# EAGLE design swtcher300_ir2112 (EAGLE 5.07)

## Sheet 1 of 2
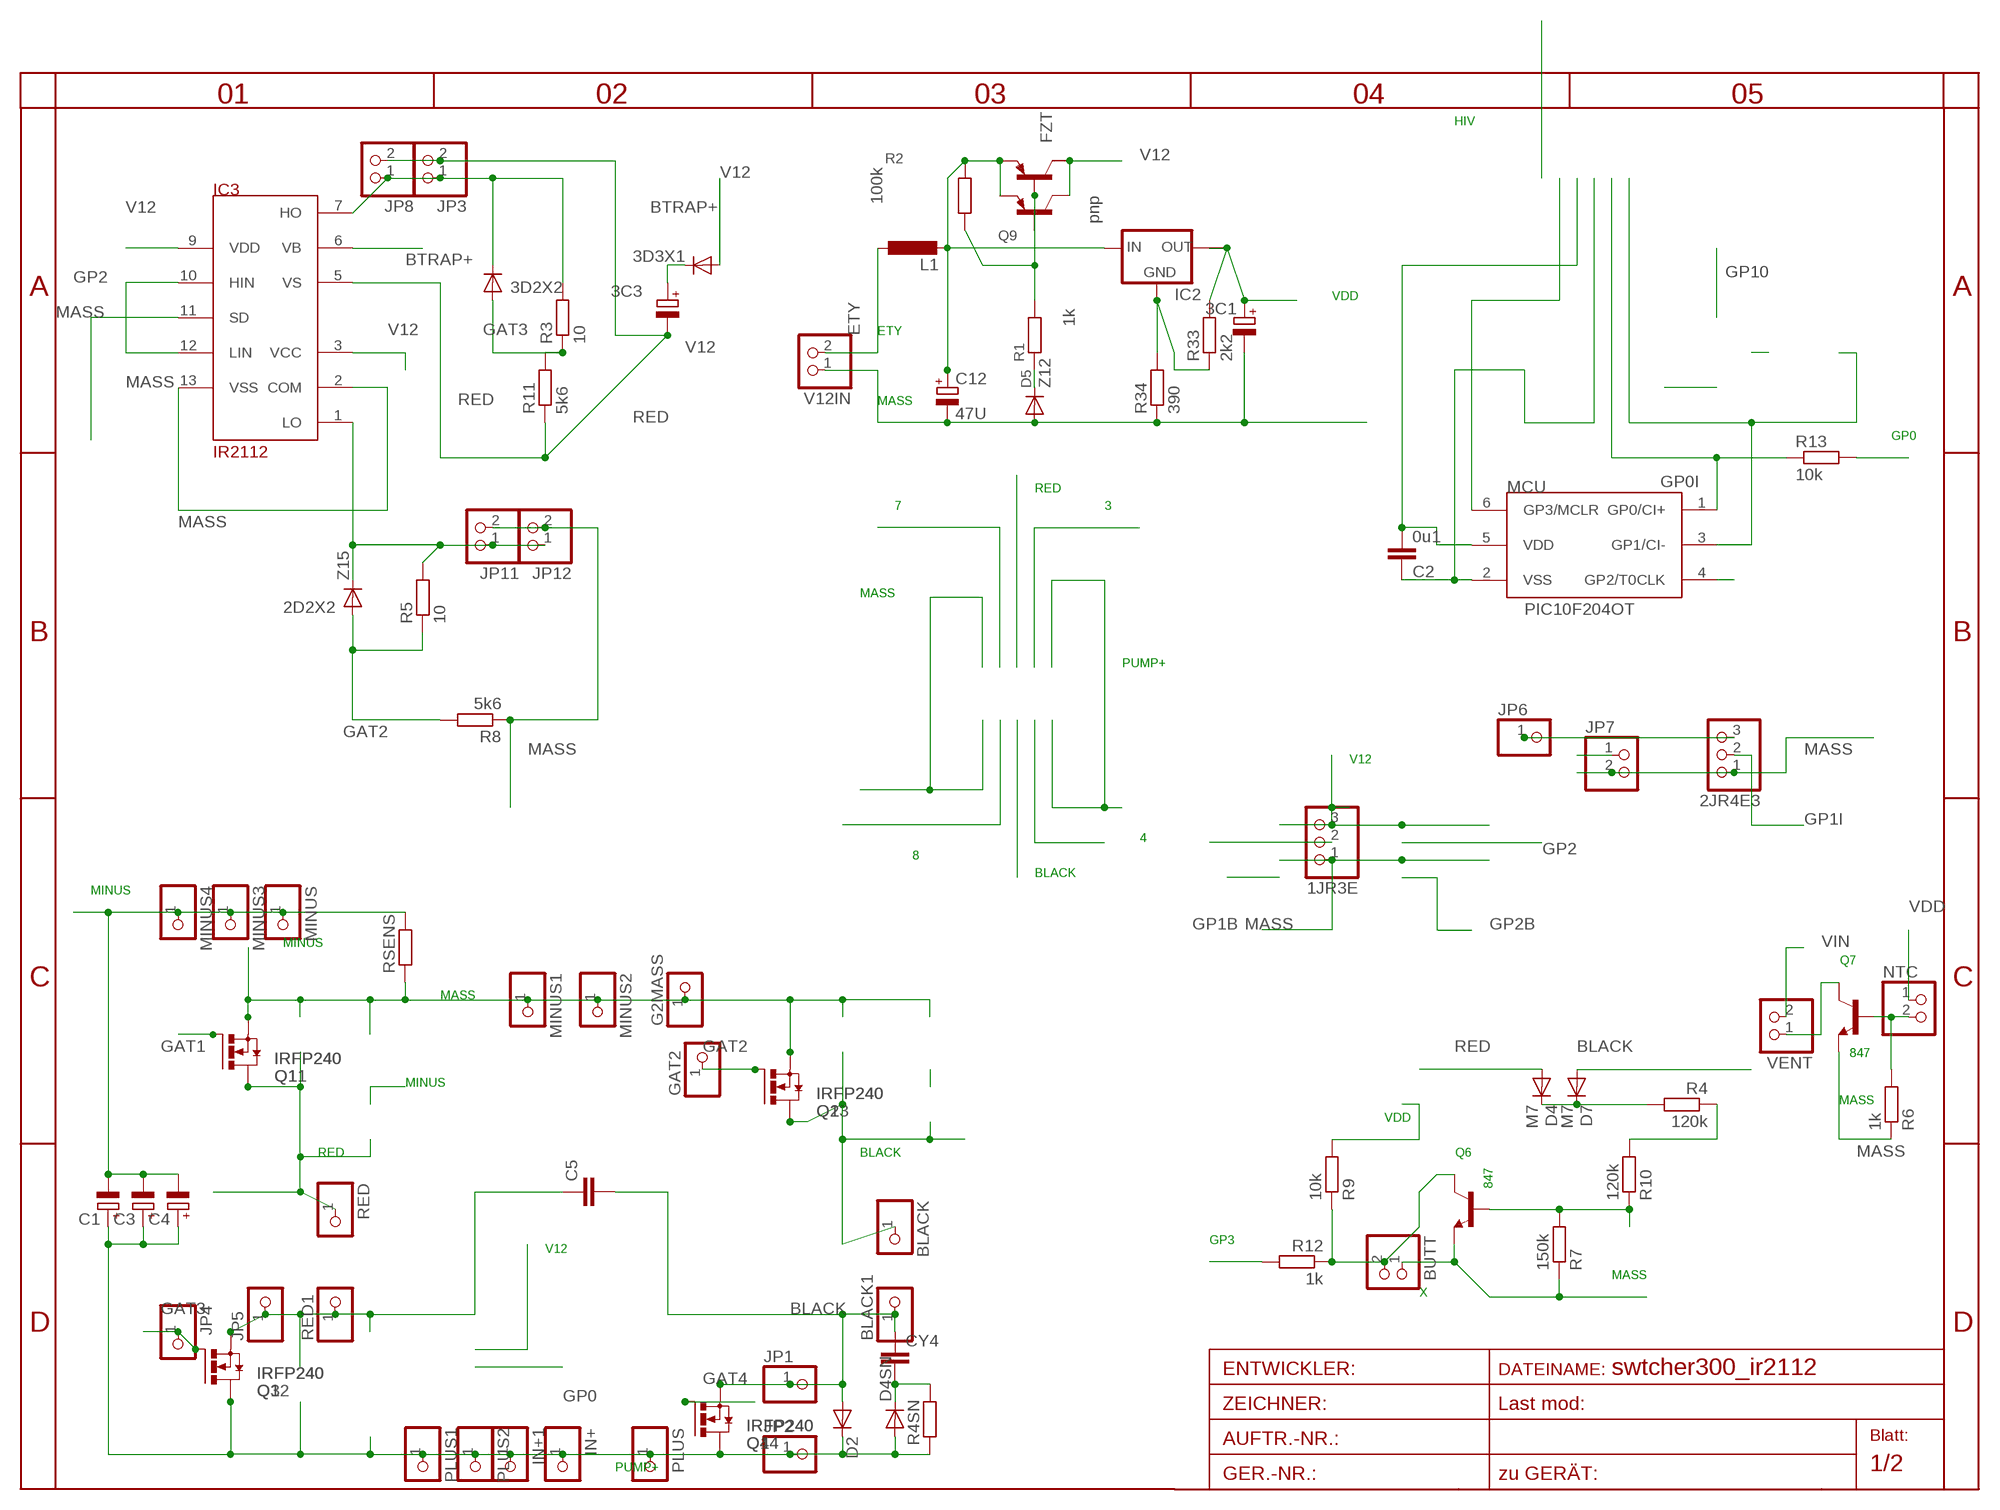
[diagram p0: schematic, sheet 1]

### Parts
1JR3E  PINHD-1X3  [1X03]
2D2X2  Z15  DIODE-D-7.5  [D-7.5]
2JR4E3  PINHD-1X3  [1X03]
3C1  CPOL-EUD  [PANASONIC_D]
3C3  CPOL-EUE2.5-5  [E2,5-5]
3D2X2  DIODE-D-7.5  [D-7.5]
3D3X1  DIODE-D-7.5  [D-7.5]
BLACK  PINHD-1X12MM3  [1X2MM3]
BLACK1  PINHD-1X12MM3  [1X2MM3]
BUTT  PINHD-1X2STR  [1X02]
C1  CPOL-EUE5-13  [E5-13]
C2  0u1  C-EUC0805  [C0805]
C3  CPOL-EUE5-13  [E5-13]
C4  CPOL-EUE5-13  [E5-13]
C5  C-EU075-032X103  [C075-032X103]
C12  47U  CPOL-EUSMCA  [SMC_A]
CY4  CXXC10B5  [XC10B5]
D2  DIODE-SMC  [SMC]
D4  M7  1N4004DO41-10  [DO41-10]
D4SN  DIODE-P1-10  [P1-10]
D5  Z12  DIODE-MINIMELF  [MINIMELF]
D7  M7  1N4004DO41-10  [DO41-10]
FZT  FZT  FZT753SMD  [SOT223]
G2MASS  PINHD-1X11MM0  [1X1MM0]
GAT2  PINHD-1X11MM0  [1X1MM0]
IC2  AP1117  [SOT223]
IC3  IR2112  [DIL14]
IN+  PINHD-1X12MM3  [1X2MM3]
IN+1  PINHD-1X12MM3  [1X2MM3]
JP1  PINHD-1X11MM0  [1X1MM0]
JP2  PINHD-1X11MM0  [1X1MM0]
JP3  PINHD-1X2STR  [1X02]
JP4  PINHD-1X11MM0  [1X1MM0]
JP5  PINHD-1X11MM0  [1X1MM0]
JP6  PINHD-1X11X0.4  [1X01]
JP7  PINHD-1X2STR  [1X02]
JP8  PINHD-1X2STR  [1X02]
JP11  PINHD-1X2STR  [1X02]
JP12  PINHD-1X2STR  [1X02]
L1  L-EU0204/5  [0204/5]
MCU  PIC10F204OT  [SOT23-6]
MINUS  PINHD-1X12MM3  [1X2MM3]
MINUS1  PINHD-1X12MM3  [1X2MM3]
MINUS2  PINHD-1X12MM3  [1X2MM3]
MINUS3  PINHD-1X12MM3  [1X2MM3]
MINUS4  PINHD-1X12MM3  [1X2MM3]
NTC  PINHD-1X2STR  [1X02]
PLUS  PINHD-1X12MM3  [1X2MM3]
PLUS1  PINHD-1X12MM3  [1X2MM3]
PLUS2  PINHD-1X12MM3  [1X2MM3]
Q1  IRFP240  [TO247BV]
Q2  IRFP240  [TO247BV]
Q3  IRFP240  [TO247BV]
Q4  IRFP240  [TO247BV]
Q6  847  BC847ALT1SMD  [SOT23]
Q7  847  BC847ALT1SMD  [SOT23]
Q9  pnp  BC857ALT1SMD  [SOT23-BEC]
Q11  IRFP240  [TO247BV]
Q12  IRFP240  [TO247BV]
Q13  IRFP240  [TO247BV]
Q14  IRFP240  [TO247BV]
R1  1k  R-EU_R0805  [R0805]
R2  100k  R-EU_R0805  [R0805]
R3  10  R-EU_0204/7  [0204/7]
R4  120k  R-EU_R1210  [R1210]
R4SN  R-EU_0207/10  [0207/10]
R5  10  R-EU_0204/7  [0204/7]
R6  1k  R-EU_R0805  [R0805]
R7  150k  R-EU_R0805  [R0805]
R8  5k6  R-EU_0207/10  [0207/10]
R9  10k  R-EU_R0805  [R0805]
R10  120k  R-EU_R1210  [R1210]
R11  5k6  R-EU_0207/10  [0207/10]
R12  1k  R-EU_R0805  [R0805]
R13  10k  R-EU_R0805  [R0805]
R33  2k2  R-EU_R0805  [R0805]
R34  390  R-EU_R0805  [R0805]
RED  PINHD-1X12MM3  [1X2MM3]
RED1  PINHD-1X12MM3  [1X2MM3]
RSENS  R-EU_0204/7  [0204/7]
V12IN  PINHD-1X2STR  [1X02]
VENT  PINHD-1X2STR  [1X02]

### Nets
BLACK: BLACK1.1 BLACK.1 C5.2 CY4.1 D2.A D7.A JP1.1 Q2.D Q4.S Q13.D Q14.S
BTRAP+: 3C3.+ 3D3X1.C IC3.6(VB)
ETY: L1.1 V12IN.2
GAT1: Q1.G Q11.G
GAT2: 2D2X2.A GAT2.1 Q2.G Q13.G R5.1 R8.2
GAT3: 3D2X2.A JP4.1 Q3.G Q12.G R3.1 R11.2
GAT4: Q4.G Q14.G
GGG: 3D2X2.C IC3.7(HO) JP3.1 JP8.1 R3.2
GP0: R13.2
GP0I: MCU.1(GP0/CI+) R13.1 ; also sheet 2
GP1I: 2JR4E3.2 MCU.3(GP1/CI-) ; also sheet 2
GP2: IC3.10(HIN) IC3.12(LIN) JP7.1 MCU.4(GP2/T0CLK)
GP2I: 1JR3E.2 ; also sheet 2
GP3: MCU.6(GP3/MCLR) R12.2 ; also sheet 2
LOGAT: 2D2X2.C IC3.1(LO) JP11.1 JP12.1 R5.2
MASS: 1JR3E.1 2JR4E3.1 3C1.- BUTT.1 C2.1 C12.- D5.A G2MASS.1 IC3.2(COM) IC3.11(SD) IC3.13(VSS) JP7.2 JP11.2 JP12.2 MCU.2(VSS) MINUS1.1 MINUS2.1 Q1.S Q2.S Q6.2(E) Q7.2(E) Q11.S Q13.S R6.1 R7.1 R8.1 R34.1 RSENS.1 V12IN.1 ; also sheet 2
MINUS: C1.- C3.- C4.- MINUS3.1 MINUS4.1 MINUS.1 RSENS.2
N$1: D4.C D7.C R4.2
N$2: FZT.1(B) Q9.B R1.2 R2.1
N$3: D5.C R1.1
N$5: Q6.1(B) R7.2 R10.1
N$7: R4.1 R10.2
N$9: NTC.2 Q7.1(B) R6.2
N$10: Q7.3(C) VENT.1
N$30: IC2.1(GND) R33.1 R34.2
PUMP+: C1.+ C3.+ C4.+ D2.C D4SN.A IN+1.1 IN+.1 JP2.1 PLUS1.1 PLUS2.1 PLUS.1 Q3.D Q4.D Q12.D Q14.D R4SN.1 ; also sheet 2
RED: 3C3.- C5.1 D4.A IC3.5(VS) JP3.2 JP5.1 JP8.2 Q1.D Q3.S Q11.D Q12.S R11.1 RED1.1 RED.1
SNUB2: CY4.2 D4SN.C R4SN.2
V12: 1JR3E.3 2JR4E3.3 3D3X1.A FZT.2(C) IC3.3(VCC) IC3.9(VDD) JP6.1 Q9.C
VDD: 3C1.+ C2.2 IC2.2(OUT) IC2.4(TAB) MCU.5(VDD) NTC.1 R9.2 R33.2 ; also sheet 2
VIN: C12.+ FZT.3(E) IC2.3(IN) L1.2 Q9.E R2.2 VENT.2
X: BUTT.2 Q6.3(C) R9.1 R12.1
Unconnected: FZT.4(C/)

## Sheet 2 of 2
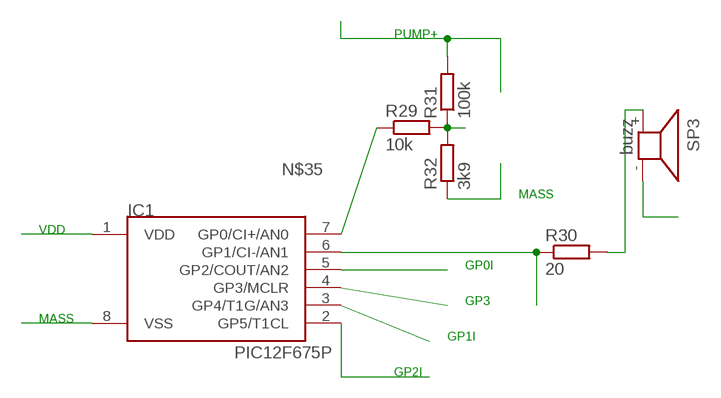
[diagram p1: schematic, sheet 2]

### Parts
IC1  PIC12F675P  [DIL8]
R29  10k  R-EU_R0805  [R0805]
R30  20  R-EU_R0805  [R0805]
R31  100k  R-EU_0207/25  [0207/25]
R32  3k9  R-EU_R0805  [R0805]
SP3  buzz  KSS12017MM  [KSS1202]

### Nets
GP0I: IC1.5(GP2/COUT/AN2) ; also sheet 1
GP1I: IC1.3(GP4/T1G/AN3) ; also sheet 1
GP2I: IC1.2(GP5/T1CL) ; also sheet 1
GP3: IC1.4(GP3/MCLR) ; also sheet 1
MASS: IC1.8(VSS) R32.1 SP3.- ; also sheet 1
N$24: R30.2 SP3.+
N$31: IC1.6(GP1/CI-/AN1) R30.1
N$34: R29.2 R31.1 R32.2
N$35: IC1.7(GP0/CI+/AN0) R29.1
PUMP+: R31.2 ; also sheet 1
VDD: IC1.1(VDD) ; also sheet 1

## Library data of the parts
1JR3E 2JR4E3 = pinhead:PINHD-1X3: PIN HEADER
2D2X2 3D2X2 3D3X1 D2 D4SN D5 = diode:DIODE-: DIODE
3C1 3C3 C1 C3 C4 = rcl:CPOL-EU: POLARIZED CAPACITOR, European symbol
BLACK BLACK1 G2MASS GAT2 IN+ IN+1 JP1 JP2 JP4-JP6 MINUS MINUS1-MINUS4 PLUS PLUS1 PLUS2 RED RED1 = pinhead:PINHD-1X1: PIN HEADER
BUTT JP3 JP7 JP8 JP11 JP12 NTC V12IN VENT = pinhead:PINHD-1X2: PIN HEADER
C2 C5 = rcl:C-EU: CAPACITOR, European symbol
C12 = rcl-2:CPOL-EU: POLARIZED CAPACITOR, European symbol
CY4 = rcl:CX: X CAPACITOR
D4 D7 = diode:1N4004: DIODE
FZT = transistor-pnp:FZT753SMD: PNP Transistor
IC1 = microchip-5:PIC12F6*: uPC nW 1k Program Flash memory 2x Timer Comparator 10b A/D converter/ 4xIN
IC2 = v-reg:AP1117
IC3 = ir2112:IR2112
L1 = rcl:L-EU: INDUCTOR, European symbol
MCU = microchip-3:PIC10F2*: uPC nW 0,25/0,5k Program Flash memory Comparator
Q1-Q4 Q11-Q14 = transistor-power:IRFP240: HEXFET Power MosFet Source: http://www.irf.com/
Q6 Q7 = transistor-npn:BC847*: NPN Transistor
Q9 = transistor-pnp:BC857*: PNP Transistror
R1-R3 R5 R8 R11 R13 R29-R34 = rcl-2:R-EU_: RESISTOR, European symbol
R4 R4SN R6 R7 R9 R10 R12 RSENS = rcl:R-EU_: RESISTOR, European symbol
SP3 = buzzer:KSS1201: SPEAKER

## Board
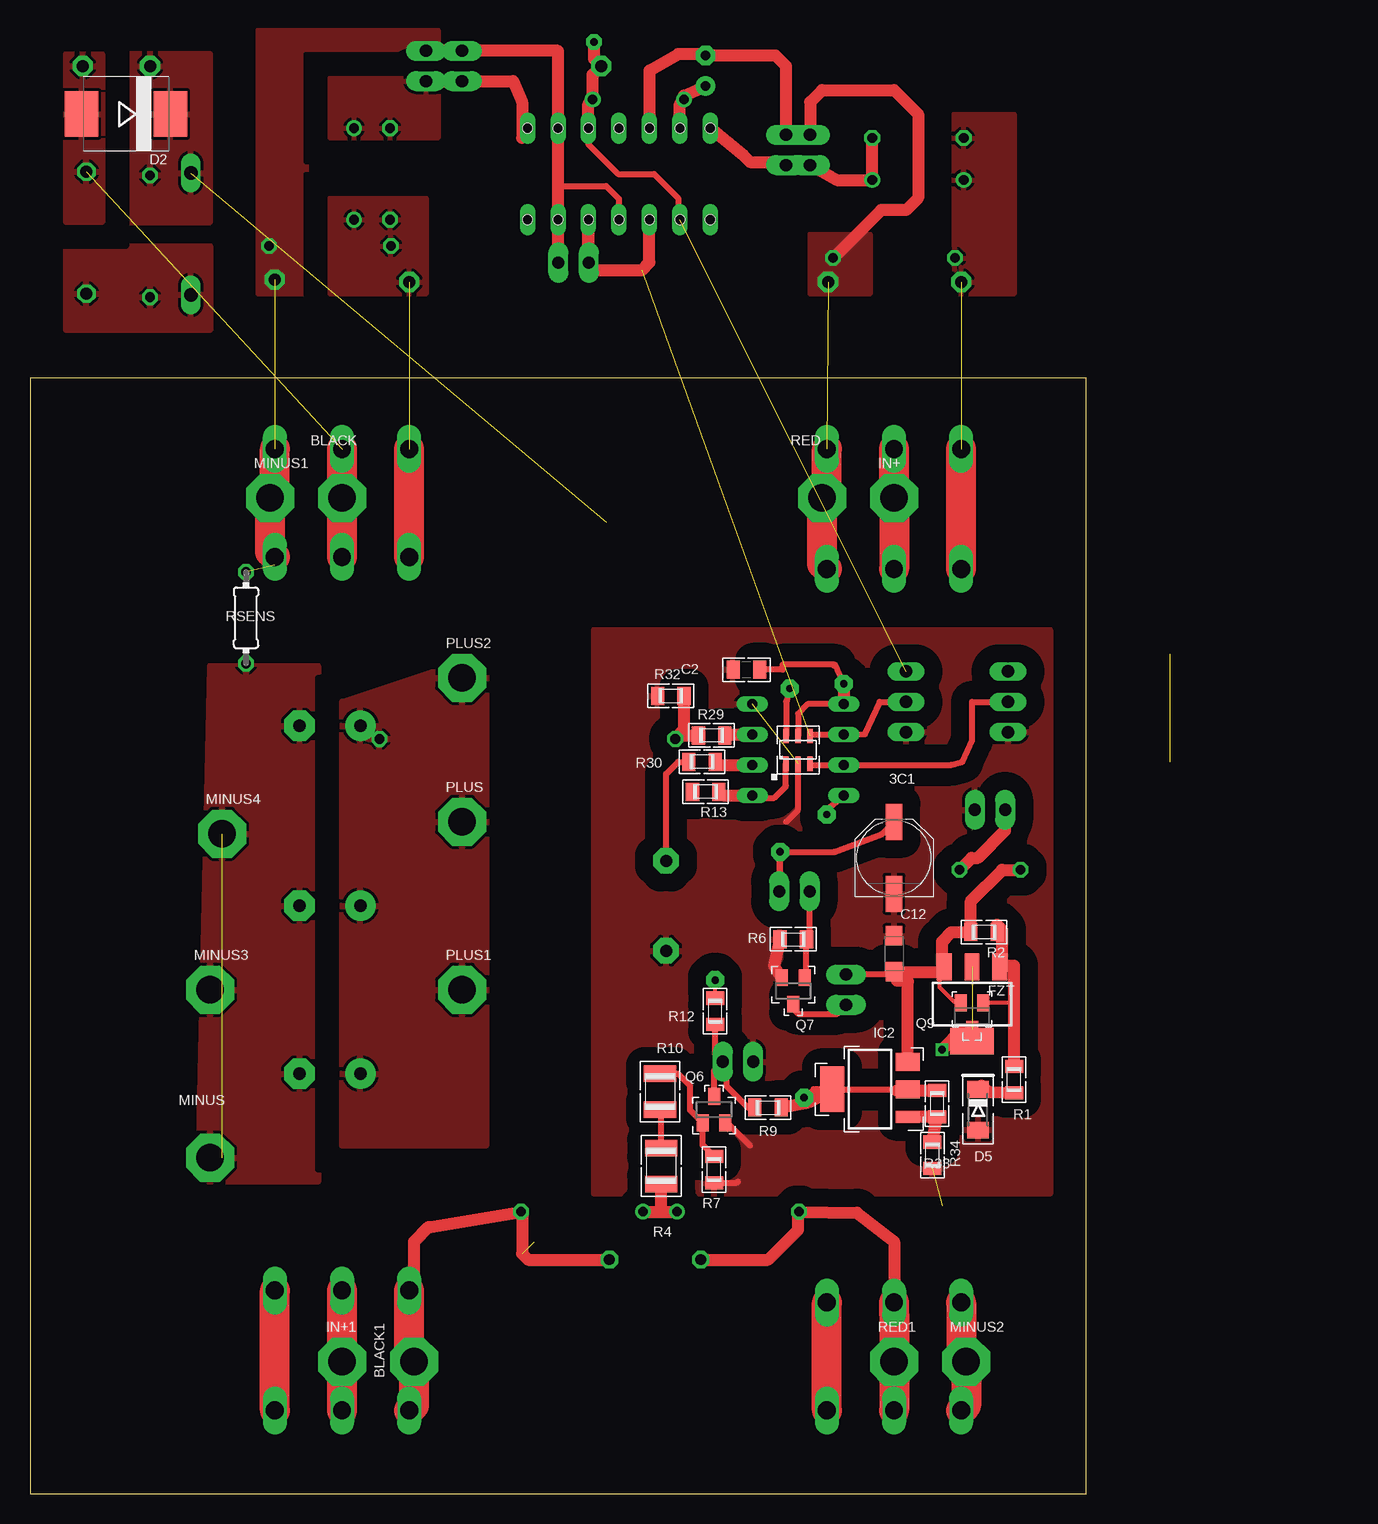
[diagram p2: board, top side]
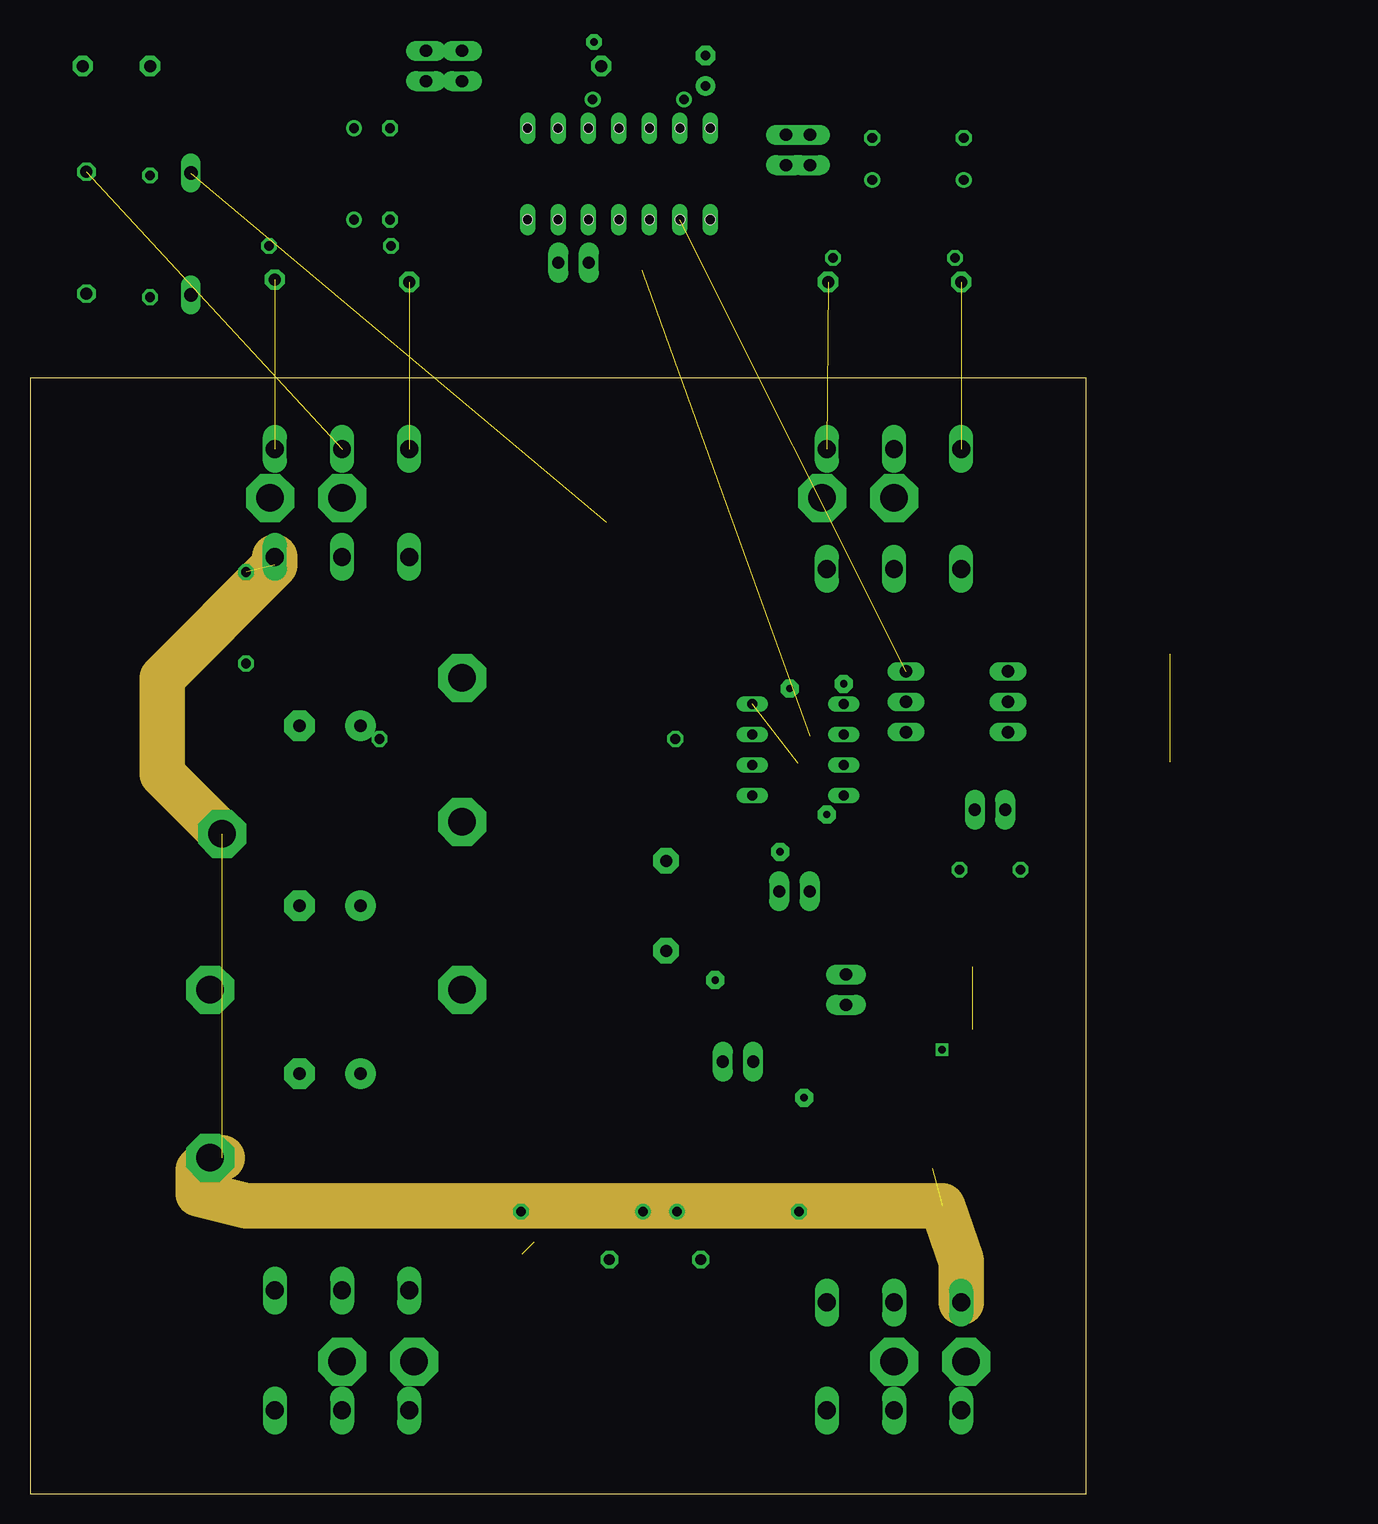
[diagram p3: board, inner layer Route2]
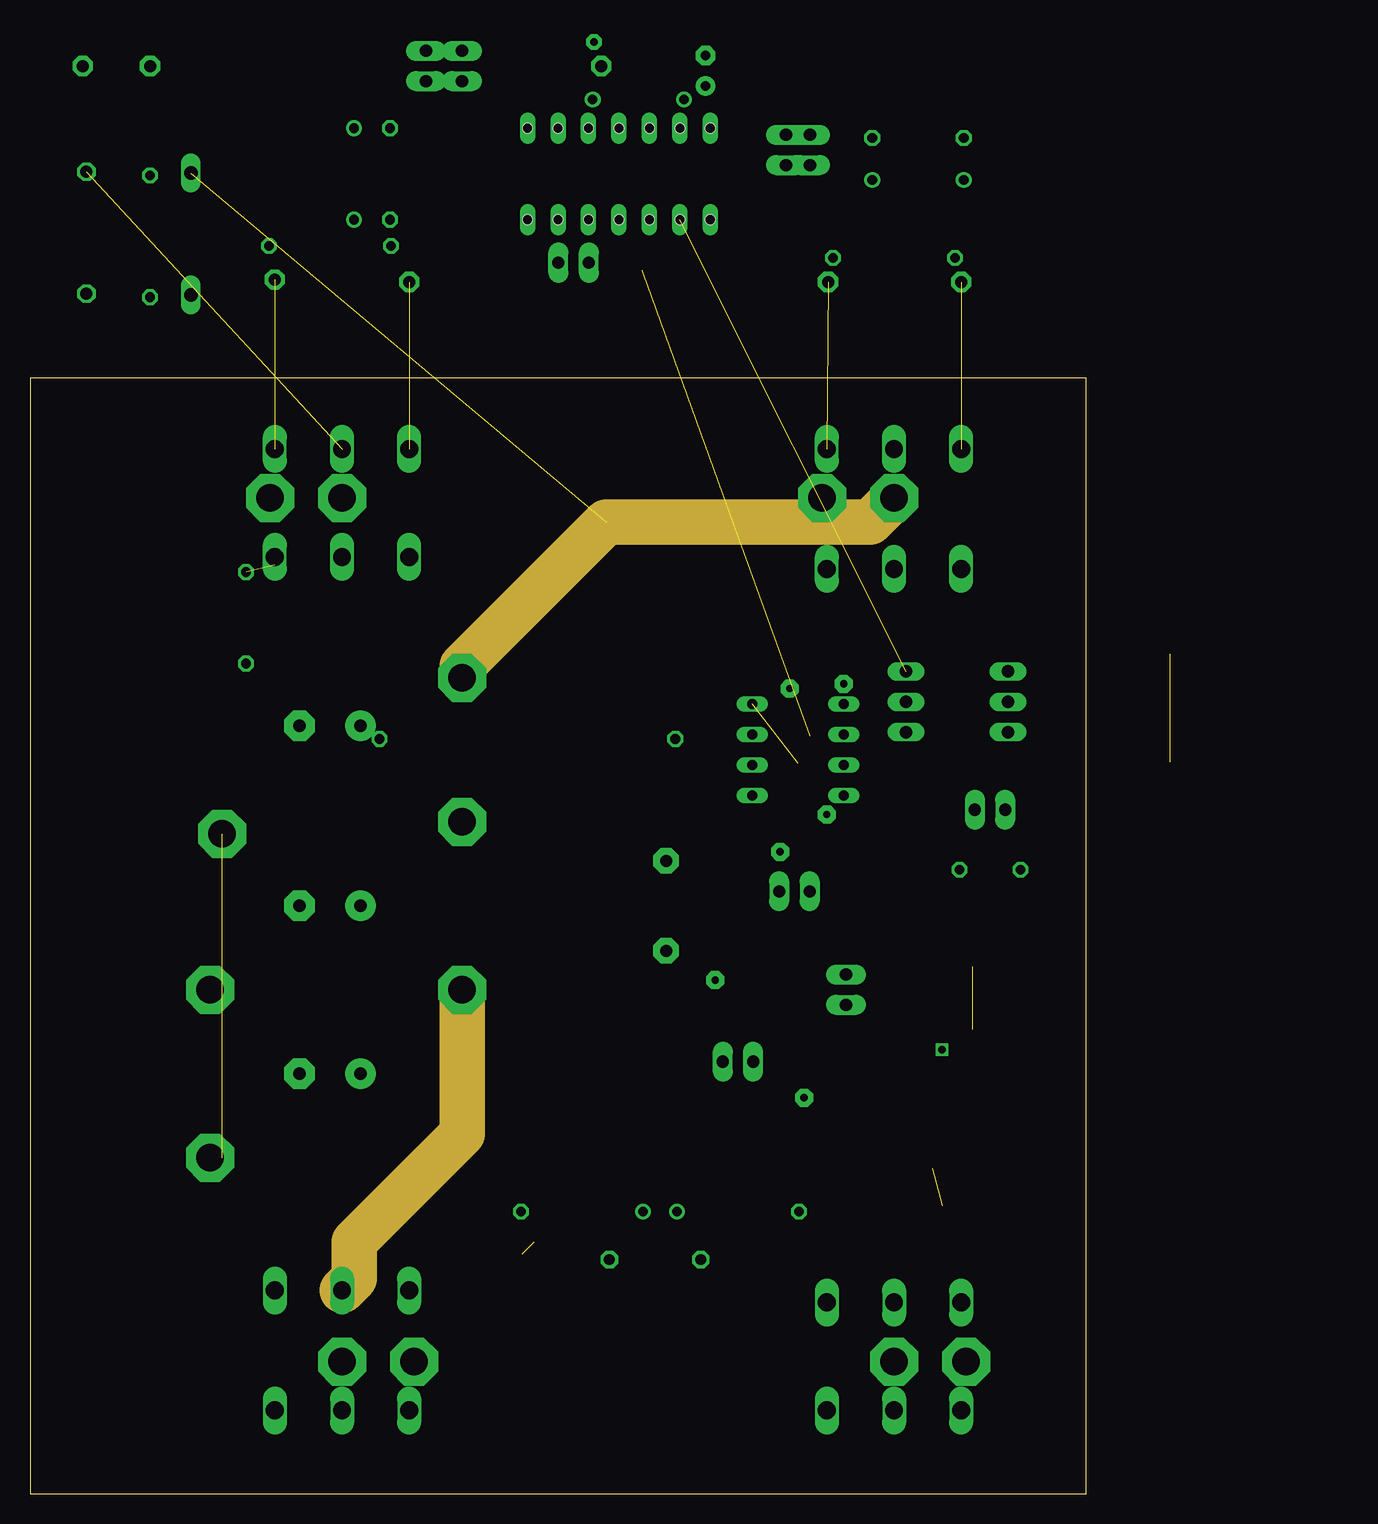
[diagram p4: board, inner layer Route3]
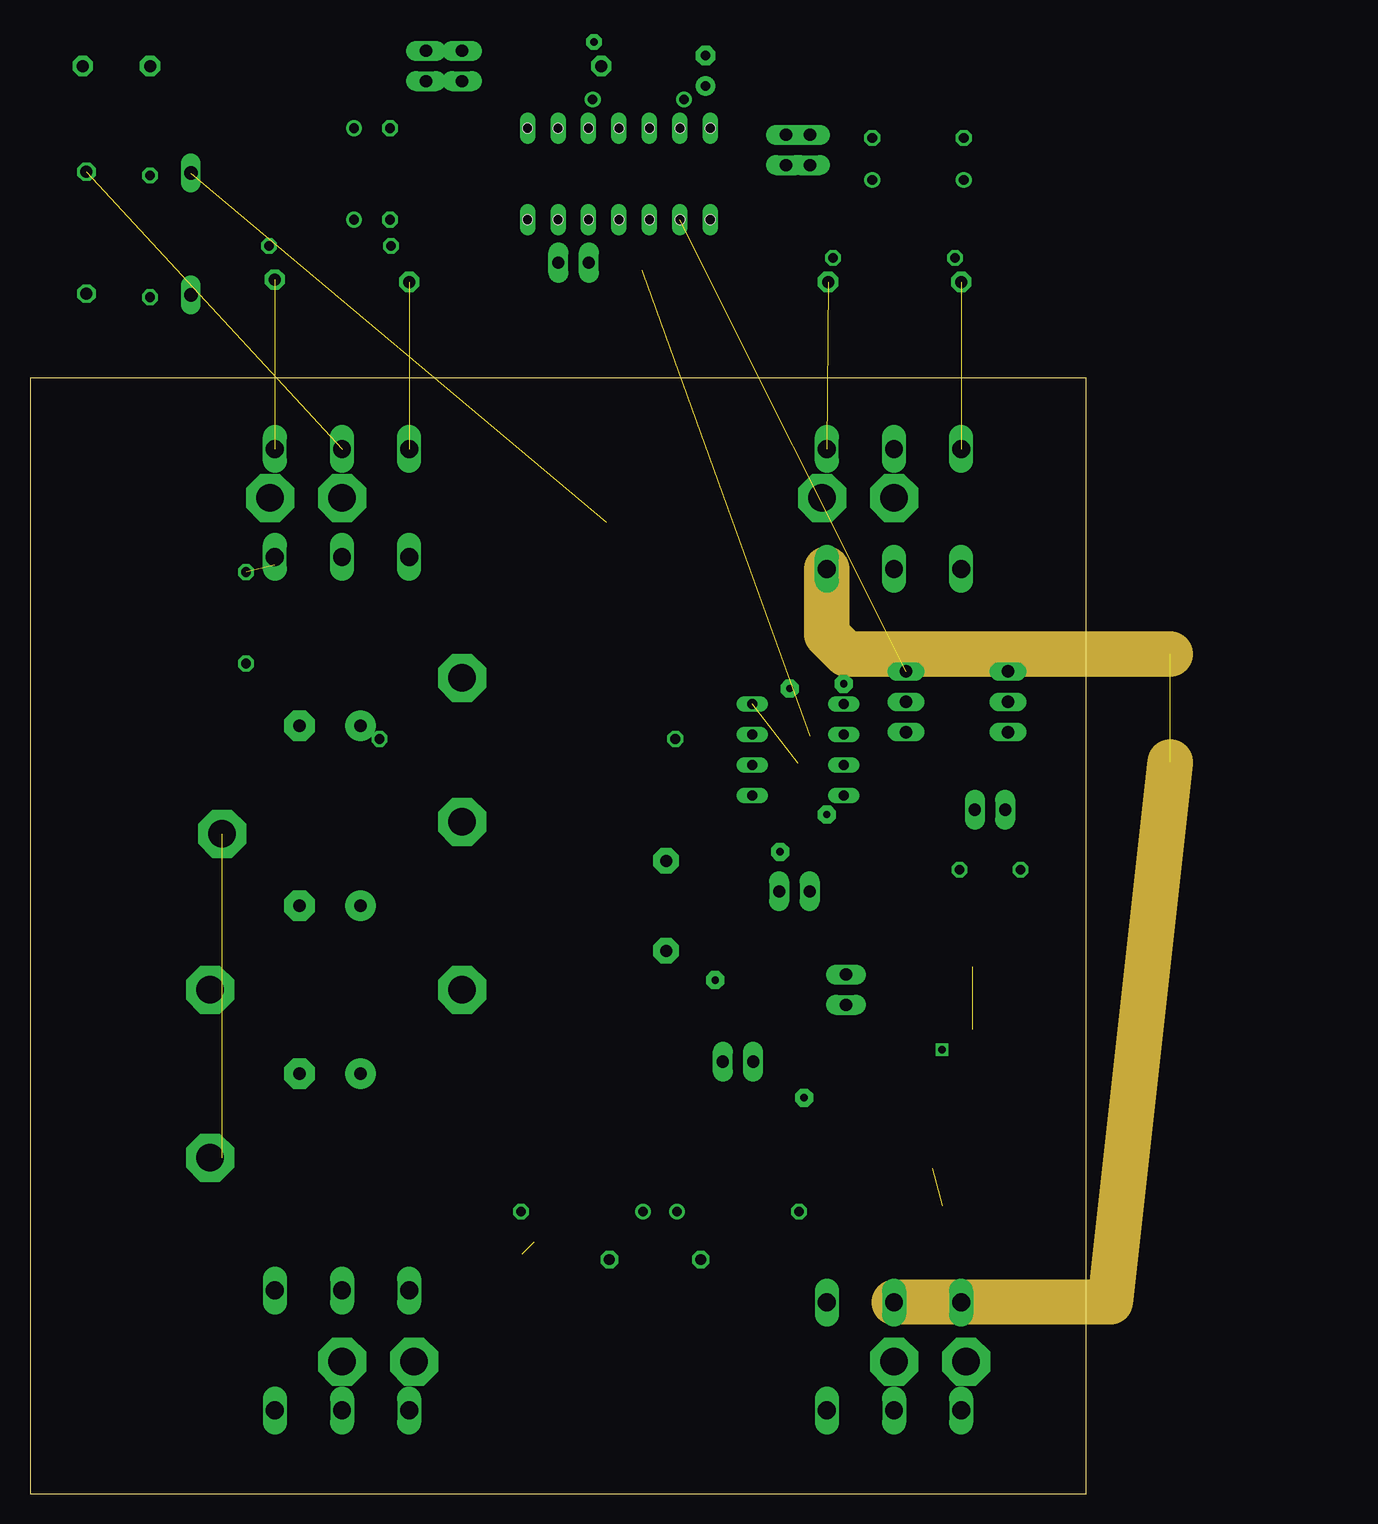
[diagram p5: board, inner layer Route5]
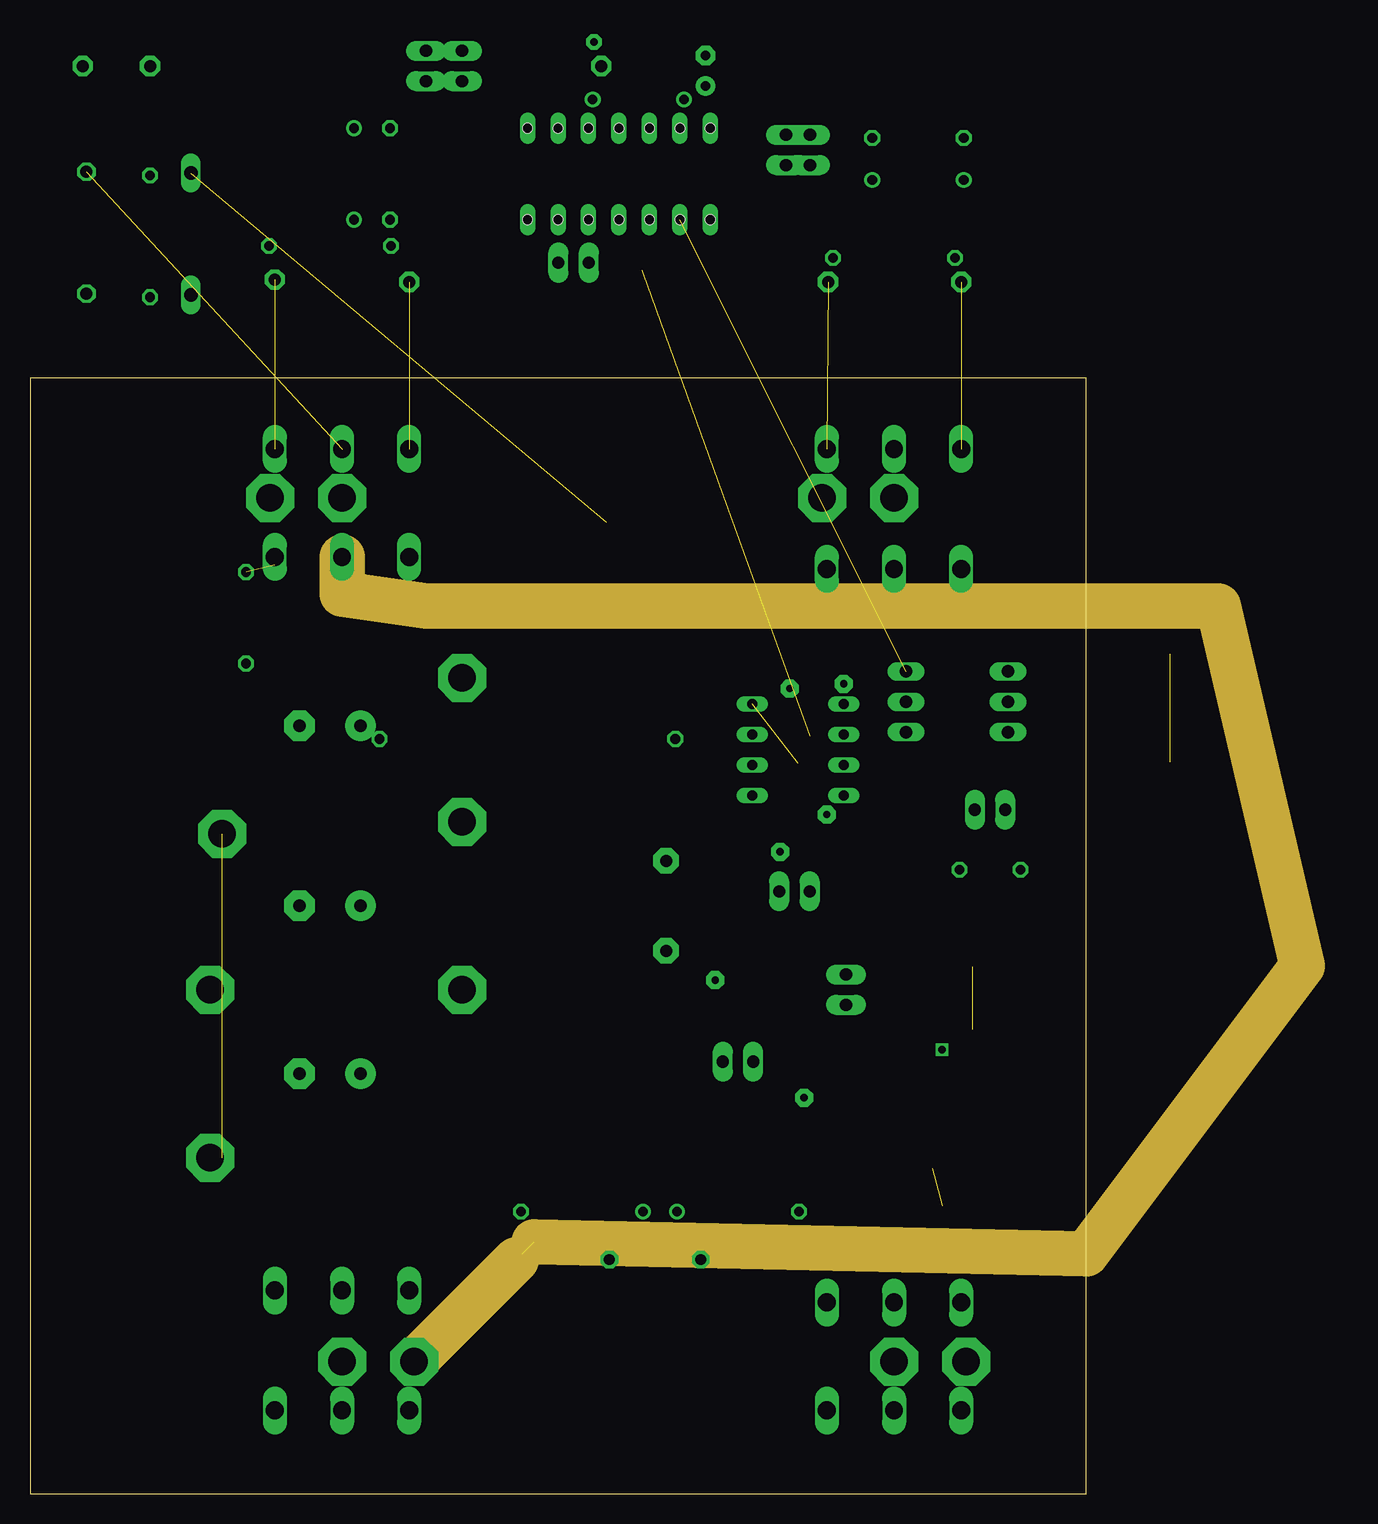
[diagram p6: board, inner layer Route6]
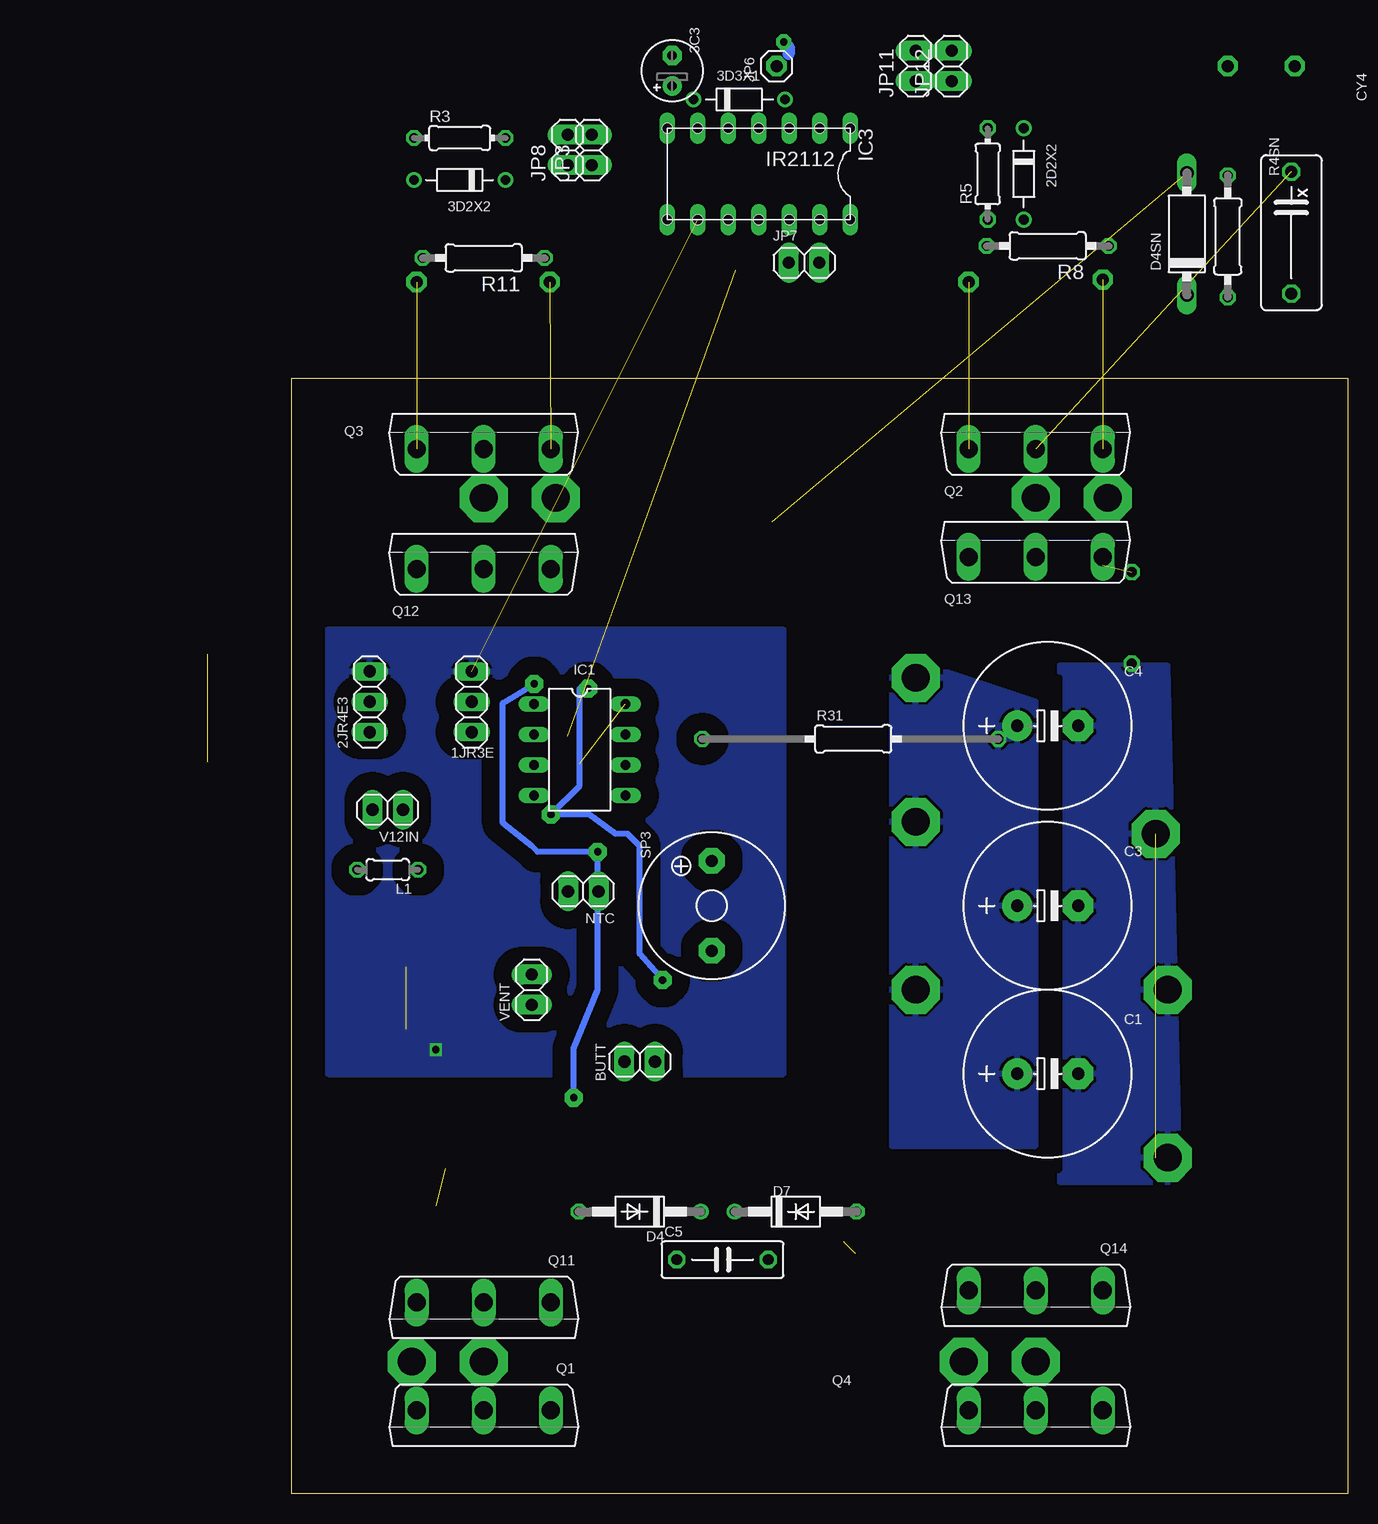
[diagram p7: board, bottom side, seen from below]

Size 88 x 93 mm. Coordinates in mm from the lower left corner, seen from the top.
Outline: 0,0 88,0 88,93 0,93 0,0
Copper layers (1*16): Top 0.035mm / dielectric 1.5mm / Bottom 0.035mm
Design rules "default *": minimum track width 10mil, minimum drill 20mil, track to track 8mil, track to pad 8mil, pad to pad 8mil, via to via 8mil, smd to smd 8mil, copper to edge 40mil, drill to drill 8mil, minimum pad ring 10mil, minimum via ring 8mil, stop-mask expansion 4mil, vias tented up to drill 0mil, thermal gap 10mil

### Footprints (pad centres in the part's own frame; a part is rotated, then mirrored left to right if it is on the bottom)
1X03 = drill 1.016 long: 1 -2.54,0; 2 0,0; 3 2.54,0
D-7.5 = drill 0.8 round: A 3.81,0; C -3.81,0
PANASONIC_D = smd 3 x 1.4: + 3,0; - -3,0
E2,5-5 = drill 0.813 pad 1.6 round: + -1.27,0 | drill 0.813 pad 1.6 octagon: - 1.27,0
1X2MM3 = drill 2.3 pad 4 octagon: 1 0,0
1X02 = drill 1.016 pad 1.676 long: 1 -1.27,0; 2 1.27,0
E5-13 = drill 1.016 pad 2.54 round: + -2.54,0 | drill 1.016 pad 2.54 octagon: - 2.54,0
C0805 = smd 1.1 x 1.5: 1 -1.1,0; 2 1.1,0
C075-032X103 = drill 0.914 octagon: 1 -3.81,0; 2 3.81,0
SMC_A = smd 1.6 x 1.4: + -1.5,0; - 1.5,0
XC10B5 = drill 1.016 octagon: 1 -5.08,0; 2 5.08,0
SMC = smd 2.8 x 3.8: A 3.7,0; C -3.7,0
DO41-10 = drill 0.8 octagon: A 5.08,0 | drill 0.8 round: C -5.08,0
P1-10 = drill 1.118 long: A 5.08,0; C -5.08,0
MINIMELF = smd 1.4 x 1.8: A 1.7,0; C -1.7,0
SOT223 = smd 1.219 x 2.235: 1 -2.311,-3.099; 2 0,-3.099; 3 2.311,-3.099 | smd 3.6 x 2.2: 4 0,3.099
1X1MM0 = drill 1 pad 1.676 octagon: 1 0,0
DIL8 = drill 0.8 long: 1 -3.81,-3.81; 2 -1.27,-3.81; 3 1.27,-3.81; 4 3.81,-3.81; 5 3.81,3.81; 6 1.27,3.81; 7 -1.27,3.81; 8 -3.81,3.81
SOT223' = smd 1 x 2: 1 -2.3,-3.15 | smd 1.5 x 2: 2 0,-3.15; 3 2.3,-3.15 | smd 3.8 x 2: 4 0,3.15
DIL14 = drill 0.8 pad 1.27 long: 1 -2.54,-3.81; 2 0,-3.81; 3 2.54,-3.81; 4 5.08,-3.81; 5 7.62,-3.81; 6 10.16,-3.81; 7 12.7,-3.81; 8 12.7,3.81; 9 10.16,3.81; 10 7.62,3.81; 11 5.08,3.81; 12 2.54,3.81; 13 0,3.81; 14 -2.54,3.81 | hole 0.8: -2.54,-3.81; 0,-3.81; 2.54,-3.81; 5.08,-3.81; 7.62,-3.81; 10.16,-3.81; 12.7,-3.81; 12.7,3.81; 10.16,3.81; 7.62,3.81; 5.08,3.81; 2.54,3.81; 0,3.81; -2.54,3.81
1X01 = drill 1 pad 1.676 octagon: 1 0,0
0204/5 = drill 0.813 octagon: 1 -2.54,0; 2 2.54,0
SOT23-6 = smd 0.45 x 1.2: 1 -1.016,-1.15; 2 0,-1.15; 3 1.016,-1.15; 4 1.016,1.15; 5 0,1.15; 6 -1.016,1.15
TO247BV = drill 1.499 long: D 0,-2.921; G -5.588,-2.921; S 5.588,-2.921
SOT23 = smd 1 x 1.4: 1 -0.95,-1.1; 2 0.95,-1.1; 3 0,1.1
SOT23-BEC = smd 1 x 1.4: B -0.95,-1.1; C 0,1.1; E 0.95,-1.1
R0805 = smd 1.1 x 1.5: 1 -1.1,0; 2 1.1,0
0204/7 = drill 0.813 octagon: 1 -3.81,0; 2 3.81,0
R1210 = smd 1.4 x 2.7: 1 -1.5,0; 2 1.5,0
0207/10 = drill 0.813 octagon: 1 -5.08,0; 2 5.08,0
0207/25 = drill 0.813 octagon: 1 -12.58,0; 2 12.08,0
KSS1202 = drill 1 pad 2.159 octagon: + 3.75,0; - -3.75,0

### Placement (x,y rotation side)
1JR3E  73,66 90 bottom
2D2X2  not placed on the board
2JR4E3  81.5,66 90 bottom
3C1  72,53 90 top
3C3  56.3,118.6 90 bottom  (outside the outline)
3D2X2  74,109.5 180 bottom  (outside the outline)
3D3X1  50.7,116.2 0 bottom  (outside the outline)
BLACK  26,83 0 top
BLACK1  32,11 90 top
BUTT  59,36 0 bottom
C1  25,35 0 bottom
C2  59.7,68.68 0 top
C3  25,49 0 bottom
C4  25,64 0 bottom
C5  52.1,19.5 0 bottom
C12  72,45 90 top
CY4  not placed on the board
D2  not placed on the board
D4  59,23.5 180 bottom
D4SN  not placed on the board
D5  79,32 270 top
D7  46,23.5 0 bottom
FZT  78.5,40.8 180 top
G2MASS  not placed on the board
GAT2  not placed on the board
IC1  64,62 270 bottom
IC2  AP1117  [SOT223']  70,33.7 90 top
IC3  44,110 180 bottom  (outside the outline)
IN+  72,83 0 top
IN+1  26,11 0 top
JP1  not placed on the board
JP2  not placed on the board
JP3  63,112 90 bottom  (outside the outline)
JP4  not placed on the board
JP5  not placed on the board
JP6  47.6,119 90 bottom  (outside the outline)
JP7  45.3,102.6 0 bottom  (outside the outline)
JP8  65,112 90 bottom  (outside the outline)
JP11  36,119 90 bottom  (outside the outline)
JP12  33,119 90 bottom  (outside the outline)
L1  80,52 180 bottom
MCU  64,62 0 top
MINUS  15,28 0 top
MINUS1  20,83 0 top
MINUS2  78,11 0 top
MINUS3  15,42 0 top
MINUS4  16,55 0 top
NTC  63.7,50.2 180 bottom
PLUS  36,56 0 top
PLUS1  36,42 0 top
PLUS2  36,68 0 top
Q1  72,4 180 bottom
Q2  26,90 0 bottom
Q3  72,90 0 bottom
Q4  26,4 180 bottom
Q6  57,32 0 top
Q7  63.6,41.9 180 top
Q9  78.5,39.8 180 top
Q11  72,13 180 bottom
Q12  72,80 0 bottom
Q13  26,81 0 bottom
Q14  26,14 180 bottom
R1  82,34.5 90 top
R2  79.5,46.8 180 top
R3  74,113 0 bottom  (outside the outline)
R4  52.6,27.3 270 top
R4SN  not placed on the board
R5  not placed on the board
R6  63.6,46.2 0 top
R7  57,27 90 top
R8  not placed on the board
R9  61.5,32.17 0 top
R10  52.5,33.5 270 top
R11  72,103 180 bottom  (outside the outline)
R12  57.1,40.2 90 top
R13  56.3,58.5 180 top
R29  56.8,63.2 180 top
R30  56,61 180 top
R31  41.2,62.9 0 bottom
R32  53.4,66.5 0 top
R33  75.6,32.5 90 top
R34  75.2,28.2 90 top
RED  66,83 0 top
RED1  72,11 0 top
RSENS  18,73 270 top
SP3  53,49 90 bottom
V12IN  80,57 180 bottom
VENT  68,42 90 bottom

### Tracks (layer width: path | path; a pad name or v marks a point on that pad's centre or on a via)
BLACK  (2 unrouted)
  Top 1: Q14.S 32,17.33 32,21 33.19,22.19 D7.A 41,23.42 41,20 41.5,19.5 C5.2
  Top 2.5: Q2.D BLACK.1 Q13.D | Q14.S 31.59,11.41 BLACK1.1 32,7.33 Q4.S
  Route6 3.81: Q13.D 26,75 33,74 99,74 106,44 88,20 42,21 | BLACK1.1 40.5,19.5
  pour Top (isolate 2): 3,120 6,120 6,106 3,106
BTRAP+
  Top 1: IC3.6 54.16,115.85 3D3X1.C 54.51,116.54 3C3.+
ETY
  Top 1: V12IN.2 81.27,55.27 79,53 78.46,53 L1.1
GAT1
  Top 2.5: Q1.G Q11.G
GAT2  (1 unrouted)
  Top 2.5: Q13.G Q2.G
  pour Top (isolate 2): 25,100 25,108 33,108 33,100
GAT3  (1 unrouted)
  Top 2.5: Q12.G Q3.G
  pour Top (isolate 2, rank 2): 77,115 82,115 82,100 77,100
GAT4
  Top 2.5: Q4.G Q14.G
GGG
  Top 1: IC3.7 59.46,111.54 60,111 62.73,111 JP3.1 JP8.1 67.23,109.5 3D2X2.C R3.2
GP0I
  Top 0.5: MCU.1 62.98,59.02 63,59 62,58 60.38,58 IC1.5
  Top 1: IC1.5 57.71,58.19 R13.1
GP1I
  Top 0.5: 2JR4E3.2 78.5,66 78.5,62.8 77.7,61 76.73,60.73 IC1.3 65.14,60.73 MCU.3
GP2  (1 unrouted)
  Top 1: IC3.10 51.62,102.62 51,102 46.5,102 46.5,105.53 JP7.1 46.57,105.43 IC3.12
GP2I
  Top 0.5: 1JR3E.2 70.8,66 69.58,63.3 IC1.2 65.14,63.27
GP3  (via drill 0.6 pad 1.5)
  Top 0.35: R12.2 v57.1,42.8
  Top 0.5: IC1.4 66.39,56.99 v66.4,56.6 | v63.3,67.1 63,66 63,63.17 MCU.6
  Bottom 0.5: v63.3,67.1 64,67.1 64,64.8 64,59 v66.4,56.6 63.2,56.6 61,55 60,55 59,54 59,45 v57.1,42.8
LOGAT
  Top 1: IC3.1 41,113 41,116 40.27,117.73 JP11.1 JP12.1 | JP12.1 32.27,117.73 32,118 32.73,118 JP12.1
  pour Top: 25,118 34,118 34,113 25,113
MASS  (5 unrouted)
  Top 0.5: Q6.2 58.1,30.9 60,29 | R7.1 58.9,25.9 59,26 | MCU.2 64,57 63,56 | IC3.11 49.08,107.92 48,109 44,109
  Top 1: R6.1 62,44 Q7.2 | IC3.13 44,107 | IC3.13 44,109 IC3.2 44,120.27 JP11.2 JP12.2 | JP7.2 44.03,103.43 IC3.13
  Top 2.5: Q2.S 20.41,83.41 MINUS1.1 20,78.49 Q13.S | Q11.S 77.59,11.41 MINUS2.1 78,7.33 Q1.S
  Route2 3.81: Q13.S 20.41,77.41 11,68 11,60 16,55 | Q11.S 77.59,19.41 76,24 18,24 14,25 14,27 15,28 16,28
  pour Top (isolate 1.5): 47,72 85,72 85,25 47,25
  pour Top (isolate 2, rank 2, no thermals): 19,122 34,122 34,120 23,120 23,119 23,104 23,100 19,100
MINUS
  pour Top (isolate 2, rank 2): 15,69 24,69 24,26 14,26
  pour Bottom (isolate 2, rank 2): 15,69 24,69 24,26 14,26
N$1
  Top 1: 52.6,23.5 R4.2 | D7.C 52.6,23.5 | 52.6,23.5 D4.C
N$2
  Top 0.35: Q9.B 81.9,40.9 82,41
  Top 1: R2.1 80.6,47.4 81,47 81,44.09 FZT.1 80.91,44 82,44 82,41 R1.2
N$3
  Top 1: R1.1 79.9,33.5 79.3,34 D5.C
N$5
  Top 0.5: R10.1 54,35 55,34 55,31.95 Q6.1 56.05,29.05 R7.2
N$7
  Top 0.5: R4.1 52.6,31.9 R10.2
N$9
  Top 0.5: NTC.2 64.97,46.47 R6.2 64.7,43.15 Q7.1
N$10
  Top 0.5: Q7.3 63.6,40.4 64,40 67.27,40 VENT.1
N$24
  Top 0.5: R30.2 54,61 53,60 SP3.+
N$30
  Top 1: IC2.1 R33.1 R34.2
N$31
  Top 1: IC1.6 57.37,60.73 R30.1
N$34
  Top 1: R29.2 54.18,63.2 R31.1 54.5,63.68 R32.2
N$35
  Top 1: IC1.7 57.9,63.27 R29.1
PUMP+  (1 unrouted)
  Top 2.5: Q3.D IN+.1 Q12.D | Q14.D IN+1.1 Q4.D
  Route3 3.81: PLUS2.1 36,69 48,81 70,81 IN+.1 | PLUS1.1 36,30 27,21 27,17.92 Q14.D
  pour Top (isolate 2, rank 2): 8,120 8,106 15,106 15,120
  pour Top (isolate 2): 26,66 38,70 38,29 26,29
  pour Bottom (isolate 2): 26,66 38,70 38,29 26,29
RED  (2 unrouted)
  Top 1: C5.1 61.5,19.5 64,22 64,23.42 D4.A 68.9,23.4 72,21 72,15 | IC3.5 51.62,118.62 54,120 56.17,120 3C3.- 62.13,119.87 63,119 JP3.2 JP8.2 65,116 66,117 72,117 74,115 74,108 73,107 70.92,107 R11.1
  Top 2.5: Q3.S 66.41,82.41 66,82 | 66,82 RED.1 | 66,82 66,77.49 Q12.S | Q1.D RED1.1 72,15 Q11.D
  Route5 3.81: Q12.S 66.41,71.59 68,70 95,70 | Q11.D 90,16 95,61
  pour Top (isolate 2, no thermals): 65,105 70,105 70,100 65,100
SNUB2
  pour Top (isolate 2, rank 2): 3,104 15,104 15,97 3,97
V12  (via drill 0.6, 0.6 pad 1.27)  (2 unrouted)
  Top 0.5: IC3.3 46.54,112.46 49,110 52,110 54,108 54,106.35 IC3.9
  Top 1: Q9.C 77.7,38.7 v76,37 | IC3.3 46.54,115.85 3D3X1.A 46.89,118.29 JP6.1 47,119.6 v47,121
  Bottom 1: 46.6,120 46.6,120.6 v47,121
  pour Bottom (isolate 1.5): 47,72 85,72 85,35 47,35
VDD  (via drill 0.6 pad 1.5)
  Top 0.406: v62.5,53.5 62.5,50.47 NTC.1
  Top 0.5: NTC.1 62.43,53.43 v62.5,53.5 67,53.5 71,55 3C1.+ | v64.5,33 65.3,33.7 IC2.4 IC2.2 | IC1.1 64.81,65.81 64,65 MCU.5 | v67.8,67.5 67.1,69.08 67,69 67,69.1 62.7,69.1 62.7,68.68 C2.2
  Top 1: IC2.4 64.85,32.62 R9.2 | R33.2 72.25,33.6 IC2.2 | v67.8,67.5 IC1.1
  Bottom 0.406: 67.5,53.5 68,54
  Bottom 0.5: v64.5,33 64.5,37.1 62.5,42 v62.5,53.5 67.5,53.5 | 68,54 70.4,55.9 70.4,65.9 v67.8,67.5
VIN
  Top 0.35: 75.79,43.5 75.79,42.21 77,41 77.45,41 Q9.E
  Top 0.5: VENT.2 71.73,43.27 72.25,42.75
  Top 1: L1.2 81,52 78.4,49.4 R2.2 76.8,46.8 76,46 76,44.09 FZT.3 75.79,43.5 C12.+ 72.25,42.75 73.15,42.65 IC2.3
X
  Top 0.5: Q6.3 57,35.27 BUTT.2 | R9.1 59.83,32.17 58,34 58,35.73 BUTT.2 | R12.1 57.1,36.63 BUTT.2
